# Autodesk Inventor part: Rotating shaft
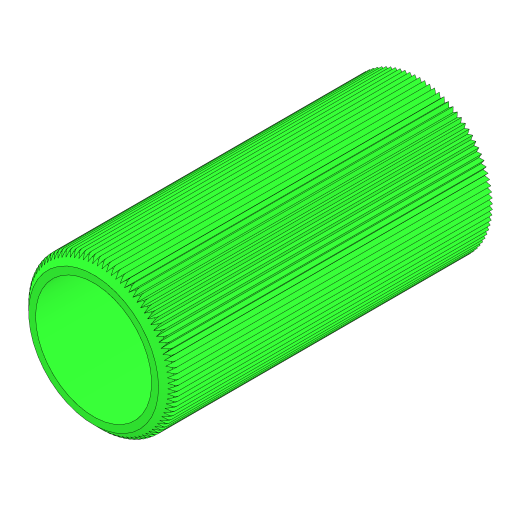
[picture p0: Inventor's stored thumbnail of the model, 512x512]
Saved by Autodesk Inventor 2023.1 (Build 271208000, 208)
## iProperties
Created: 2020-02
Part Number: Rotating shaft
Material: Generic
Document SubType Name: Modeling
Designer: ftrauzettel
Density: 1 g/cm^3
Appearance: Default
Sending System: SolidWorks 2016
Last Author: Pam
Last Saved: 2020-10-15
Author: ftrauzettel
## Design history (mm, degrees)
feature "Tap Drill Slot for M2 Tap1"
body "Solid1"
